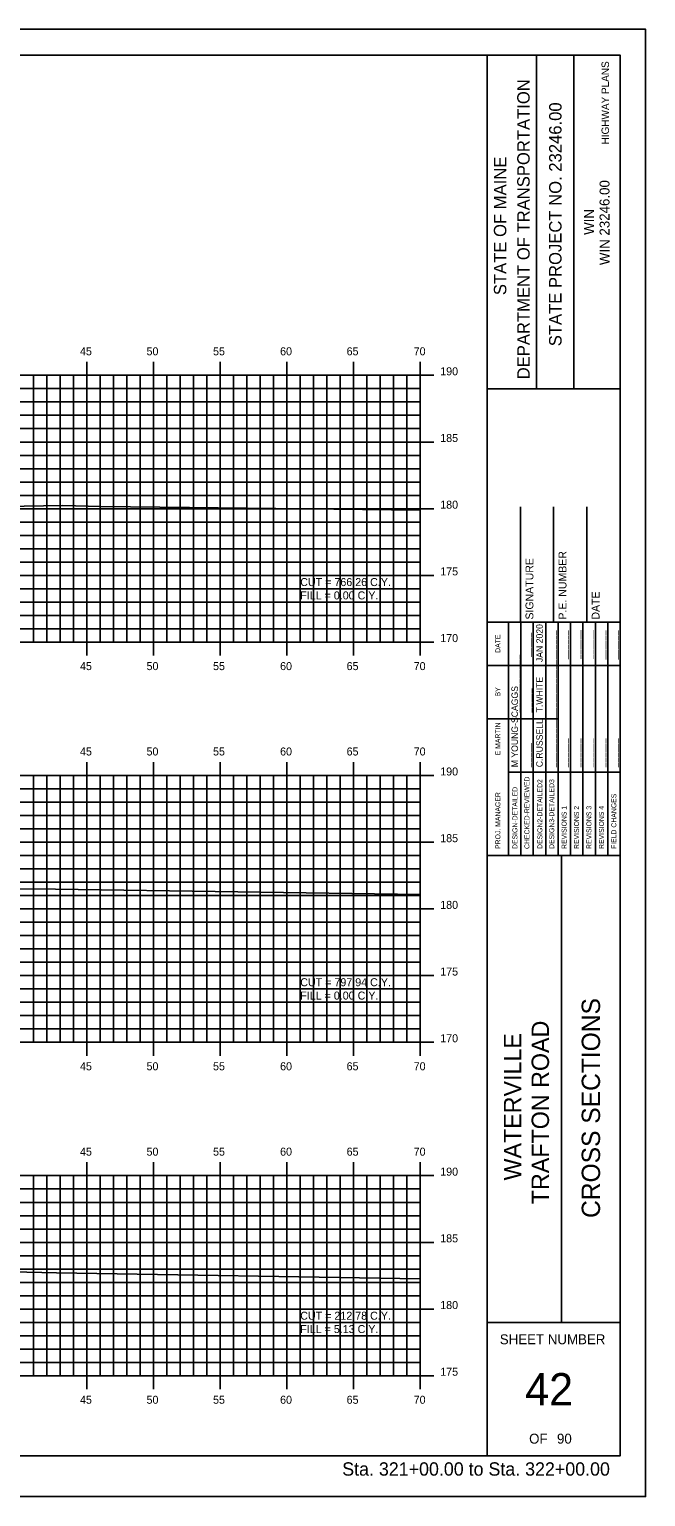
# Model space of a CAD drawing. Extents: x 1139872 to 1140042, y 608981 to 609091.
# Drawn here: x 1139995.6 to 1140041.9, y 608981.3 to 609091.3 of the extents above; entities that cross this region are included whole.
import ezdxf

# ---------------------------------------------------------------- set-up
doc = ezdxf.new("R2010")
doc.units = 0
for name, color, linetype in [('BORDER', 7, 'Continuous'), ('D_Text_Standard', 7, 'Continuous'), ('H_V ANNOTATION', 7, 'Continuous'), ('HIGHWAY_TITLE', 7, 'Continuous'), ('MAJOR', 7, 'Continuous'), ('MINOR', 7, 'Continuous'), ('PLOT BOUNDARY', 7, 'Continuous'), ('S_Roadway_Centerline', 7, 'Continuous')]:
    doc.layers.add(name, color=color, linetype=linetype)

msp = doc.modelspace()

# ---------------------------------------------------------------- linework, layer by layer
at = {"layer": 'BORDER'}
for p, q in [((1140029.98, 608984.34), (1140029.98, 609089.34)), ((1140033.7, 609064.33), (1140033.7, 609089.33)), ((1140036.5, 609064.33), (1140036.5, 609089.33)), ((1140029.98, 609064.33), (1140039.98, 609064.33)), ((1140032.48, 609046.84), (1140032.48, 609055.49)), ((1140034.98, 609046.84), (1140034.98, 609055.49)), ((1140037.48, 609046.84), (1140037.48, 609055.49)), ((1140029.98, 609046.84), (1140039.98, 609046.84)), ((1140029.98, 609029.34), (1140039.98, 609029.34)), ((1140035.57, 608994.34), (1140035.57, 609029.34)), ((1140029.98, 608994.34), (1140039.98, 608994.34))]:
    msp.add_line(p, q, dxfattribs=at)
msp.add_lwpolyline([(1139879.98, 608984.34), (1140039.98, 608984.34), (1140039.98, 609089.34), (1139879.98, 609089.34)], close=True, dxfattribs=at)
for points in [[(1140031.59, 609043.59), (1140031.59, 609046.84)], [(1140031.59, 609029.34), (1140031.59, 609046.13)], [(1140032.52, 609029.34), (1140032.52, 609046.84)], [(1140033.45, 609046.84), (1140033.45, 609029.34)], [(1140034.39, 609029.34), (1140034.39, 609046.84)], [(1140035.32, 609029.34), (1140035.32, 609046.84)], [(1140036.25, 609029.34), (1140036.25, 609046.84)], [(1140037.18, 609029.34), (1140037.18, 609046.84)], [(1140038.11, 609029.34), (1140038.11, 609046.84)], [(1140039.04, 609029.34), (1140039.04, 609046.84)], [(1140029.98, 609043.59), (1140039.98, 609043.59)], [(1140029.98, 609039.59), (1140031.59, 609039.59)], [(1140031.59, 609039.59), (1140035.32, 609039.59)], [(1140031.59, 609035.59), (1140039.98, 609035.59)]]:
    msp.add_lwpolyline(points, dxfattribs=at)
at = {"layer": 'MAJOR'}
for p, q in [((1139999.97, 609066.34), (1139999.97, 609065.34)), ((1140004.97, 609066.34), (1140004.97, 609065.34)), ((1140009.97, 609066.34), (1140009.97, 609065.34)), ((1140014.97, 609066.34), (1140014.97, 609065.34)), ((1140019.97, 609066.34), (1140019.97, 609065.34)), ((1140024.97, 609066.34), (1140024.97, 609065.34)), ((1139884.97, 609065.34), (1140024.97, 609065.34)), ((1139884.97, 609065.34), (1140024.97, 609065.34)), ((1139999.97, 609045.34), (1139999.97, 609065.34)), ((1140004.97, 609045.34), (1140004.97, 609065.34)), ((1140009.97, 609045.34), (1140009.97, 609065.34)), ((1140014.97, 609045.34), (1140014.97, 609065.34)), ((1140019.97, 609045.34), (1140019.97, 609065.34)), ((1140025.98, 609065.34), (1140023.97, 609065.34)), ((1140024.97, 609045.34), (1140024.97, 609065.34)), ((1140024.97, 609045.34), (1140024.97, 609065.34)), ((1139884.97, 609060.34), (1140024.97, 609060.34)), ((1140025.98, 609060.34), (1140023.97, 609060.34)), ((1139884.97, 609055.34), (1140024.97, 609055.34)), ((1140025.98, 609055.34), (1140023.97, 609055.34)), ((1139884.97, 609050.34), (1140024.97, 609050.34)), ((1140025.98, 609050.34), (1140023.97, 609050.34)), ((1139884.97, 609045.34), (1140024.97, 609045.34)), ((1139884.97, 609045.34), (1140024.97, 609045.34)), ((1139999.97, 609044.33), (1139999.97, 609045.34)), ((1140004.97, 609044.33), (1140004.97, 609045.34)), ((1140009.97, 609044.33), (1140009.97, 609045.34)), ((1140014.97, 609044.33), (1140014.97, 609045.34)), ((1140019.97, 609044.33), (1140019.97, 609045.34)), ((1140025.98, 609045.34), (1140023.97, 609045.34)), ((1140024.97, 609044.33), (1140024.97, 609045.34)), ((1139999.97, 609036.34), (1139999.97, 609035.34)), ((1140004.97, 609036.34), (1140004.97, 609035.34)), ((1140009.97, 609036.34), (1140009.97, 609035.34)), ((1140014.97, 609036.34), (1140014.97, 609035.34)), ((1140019.97, 609036.34), (1140019.97, 609035.34)), ((1140024.97, 609036.34), (1140024.97, 609035.34)), ((1139884.97, 609035.34), (1140024.97, 609035.34)), ((1139884.97, 609035.34), (1140024.97, 609035.34)), ((1139999.97, 609015.34), (1139999.97, 609035.34)), ((1140004.97, 609015.34), (1140004.97, 609035.34)), ((1140009.97, 609015.34), (1140009.97, 609035.34)), ((1140014.97, 609015.34), (1140014.97, 609035.34)), ((1140019.97, 609015.34), (1140019.97, 609035.34)), ((1140025.98, 609035.34), (1140023.97, 609035.34)), ((1140024.97, 609015.34), (1140024.97, 609035.34)), ((1140024.97, 609015.34), (1140024.97, 609035.34)), ((1139884.97, 609030.34), (1140024.97, 609030.34)), ((1140025.98, 609030.34), (1140023.97, 609030.34)), ((1139884.97, 609025.34), (1140024.97, 609025.34)), ((1140025.98, 609025.34), (1140023.97, 609025.34)), ((1139884.97, 609020.34), (1140024.97, 609020.34)), ((1140025.98, 609020.34), (1140023.97, 609020.34)), ((1139884.97, 609015.34), (1140024.97, 609015.34)), ((1139884.97, 609015.34), (1140024.97, 609015.34)), ((1139999.97, 609014.33), (1139999.97, 609015.34)), ((1140004.97, 609014.33), (1140004.97, 609015.34)), ((1140009.97, 609014.33), (1140009.97, 609015.34)), ((1140014.97, 609014.33), (1140014.97, 609015.34)), ((1140019.97, 609014.33), (1140019.97, 609015.34)), ((1140025.98, 609015.34), (1140023.97, 609015.34)), ((1140024.97, 609014.33), (1140024.97, 609015.34)), ((1139999.97, 609006.34), (1139999.97, 609005.34)), ((1140004.97, 609006.34), (1140004.97, 609005.34)), ((1140009.97, 609006.34), (1140009.97, 609005.34)), ((1140014.97, 609006.34), (1140014.97, 609005.34)), ((1140019.97, 609006.34), (1140019.97, 609005.34)), ((1140024.97, 609006.34), (1140024.97, 609005.34)), ((1139884.97, 609005.34), (1140024.97, 609005.34)), ((1139884.97, 609005.34), (1140024.97, 609005.34)), ((1139999.97, 608990.34), (1139999.97, 609005.34)), ((1140004.97, 608990.34), (1140004.97, 609005.34)), ((1140009.97, 608990.34), (1140009.97, 609005.34)), ((1140014.97, 608990.34), (1140014.97, 609005.34)), ((1140019.97, 608990.34), (1140019.97, 609005.34)), ((1140025.98, 609005.34), (1140023.97, 609005.34)), ((1140024.97, 608990.34), (1140024.97, 609005.34)), ((1140024.97, 608990.34), (1140024.97, 609005.34)), ((1139884.97, 609000.34), (1140024.97, 609000.34)), ((1140025.98, 609000.34), (1140023.97, 609000.34)), ((1139884.97, 608995.34), (1140024.97, 608995.34)), ((1140025.98, 608995.34), (1140023.97, 608995.34)), ((1139884.97, 608990.34), (1140024.97, 608990.34)), ((1139884.97, 608990.34), (1140024.97, 608990.34)), ((1139999.97, 608989.33), (1139999.97, 608990.34)), ((1140004.97, 608989.33), (1140004.97, 608990.34)), ((1140009.97, 608989.33), (1140009.97, 608990.34)), ((1140014.97, 608989.33), (1140014.97, 608990.34)), ((1140019.97, 608989.33), (1140019.97, 608990.34)), ((1140025.98, 608990.34), (1140023.97, 608990.34)), ((1140024.97, 608989.33), (1140024.97, 608990.34))]:
    msp.add_line(p, q, dxfattribs=at)
at = {"layer": 'MINOR'}
for p, q in [((1139995.97, 609045.34), (1139995.97, 609065.34)), ((1139996.97, 609045.34), (1139996.97, 609065.34)), ((1139997.97, 609045.34), (1139997.97, 609065.34)), ((1139998.97, 609045.34), (1139998.97, 609065.34)), ((1140000.97, 609045.34), (1140000.97, 609065.34)), ((1140001.97, 609045.34), (1140001.97, 609065.34)), ((1140002.97, 609045.34), (1140002.97, 609065.34)), ((1140003.97, 609045.34), (1140003.97, 609065.34)), ((1140005.97, 609045.34), (1140005.97, 609065.34)), ((1140006.97, 609045.34), (1140006.97, 609065.34)), ((1140007.97, 609045.34), (1140007.97, 609065.34)), ((1140008.97, 609045.34), (1140008.97, 609065.34)), ((1140010.97, 609045.34), (1140010.97, 609065.34)), ((1140011.97, 609045.34), (1140011.97, 609065.34)), ((1140012.97, 609045.34), (1140012.97, 609065.34)), ((1140013.97, 609045.34), (1140013.97, 609065.34)), ((1140015.97, 609045.34), (1140015.97, 609065.34)), ((1140016.97, 609045.34), (1140016.97, 609065.34)), ((1140017.97, 609045.34), (1140017.97, 609065.34)), ((1140018.97, 609045.34), (1140018.97, 609065.34)), ((1140020.97, 609045.34), (1140020.97, 609065.34)), ((1140021.97, 609045.34), (1140021.97, 609065.34)), ((1140022.97, 609045.34), (1140022.97, 609065.34)), ((1140023.97, 609045.34), (1140023.97, 609065.34)), ((1139884.97, 609064.34), (1140024.97, 609064.34)), ((1140024.97, 609064.34), (1140023.97, 609064.34)), ((1139884.97, 609063.34), (1140024.97, 609063.34)), ((1139884.97, 609062.34), (1140024.97, 609062.34)), ((1140024.97, 609063.34), (1140023.97, 609063.34)), ((1140024.97, 609062.34), (1140023.97, 609062.34)), ((1139884.97, 609061.34), (1140024.97, 609061.34)), ((1140024.97, 609061.34), (1140023.97, 609061.34)), ((1139884.97, 609059.34), (1140024.97, 609059.34)), ((1140024.97, 609059.34), (1140023.97, 609059.34)), ((1139884.97, 609058.34), (1140024.97, 609058.34)), ((1140024.97, 609058.34), (1140023.97, 609058.34)), ((1139884.97, 609057.34), (1140024.97, 609057.34)), ((1140024.97, 609057.34), (1140023.97, 609057.34)), ((1139884.97, 609056.34), (1140024.97, 609056.34)), ((1140024.97, 609056.34), (1140023.97, 609056.34)), ((1139884.97, 609054.34), (1140024.97, 609054.34)), ((1140024.97, 609054.34), (1140023.97, 609054.34)), ((1139884.97, 609053.34), (1140024.97, 609053.34)), ((1140024.97, 609053.34), (1140023.97, 609053.34)), ((1139884.97, 609052.34), (1140024.97, 609052.34)), ((1139884.97, 609051.34), (1140024.97, 609051.34)), ((1140024.97, 609052.34), (1140023.97, 609052.34)), ((1140024.97, 609051.34), (1140023.97, 609051.34)), ((1139884.97, 609049.34), (1140024.97, 609049.34)), ((1140024.97, 609049.34), (1140023.97, 609049.34)), ((1139884.97, 609048.34), (1140024.97, 609048.34)), ((1140024.97, 609048.34), (1140023.97, 609048.34)), ((1139884.97, 609047.34), (1140024.97, 609047.34)), ((1140024.97, 609047.34), (1140023.97, 609047.34)), ((1139884.97, 609046.34), (1140024.97, 609046.34)), ((1140024.97, 609046.34), (1140023.97, 609046.34)), ((1139995.97, 609015.34), (1139995.97, 609035.34)), ((1139996.97, 609015.34), (1139996.97, 609035.34)), ((1139997.97, 609015.34), (1139997.97, 609035.34)), ((1139998.97, 609015.34), (1139998.97, 609035.34)), ((1140000.97, 609015.34), (1140000.97, 609035.34)), ((1140001.97, 609015.34), (1140001.97, 609035.34)), ((1140002.97, 609015.34), (1140002.97, 609035.34)), ((1140003.97, 609015.34), (1140003.97, 609035.34)), ((1140005.97, 609015.34), (1140005.97, 609035.34)), ((1140006.97, 609015.34), (1140006.97, 609035.34)), ((1140007.97, 609015.34), (1140007.97, 609035.34)), ((1140008.97, 609015.34), (1140008.97, 609035.34)), ((1140010.97, 609015.34), (1140010.97, 609035.34)), ((1140011.97, 609015.34), (1140011.97, 609035.34)), ((1140012.97, 609015.34), (1140012.97, 609035.34)), ((1140013.97, 609015.34), (1140013.97, 609035.34)), ((1140015.97, 609015.34), (1140015.97, 609035.34)), ((1140016.97, 609015.34), (1140016.97, 609035.34)), ((1140017.97, 609015.34), (1140017.97, 609035.34)), ((1140018.97, 609015.34), (1140018.97, 609035.34)), ((1140020.97, 609015.34), (1140020.97, 609035.34)), ((1140021.97, 609015.34), (1140021.97, 609035.34)), ((1140022.97, 609015.34), (1140022.97, 609035.34)), ((1140023.97, 609015.34), (1140023.97, 609035.34)), ((1139884.97, 609034.34), (1140024.97, 609034.34)), ((1140024.97, 609034.34), (1140023.97, 609034.34)), ((1139884.97, 609033.34), (1140024.97, 609033.34)), ((1140024.97, 609033.34), (1140023.97, 609033.34)), ((1139884.97, 609032.34), (1140024.97, 609032.34)), ((1140024.97, 609032.34), (1140023.97, 609032.34)), ((1139884.97, 609031.34), (1140024.97, 609031.34)), ((1140024.97, 609031.34), (1140023.97, 609031.34)), ((1139884.97, 609029.34), (1140024.97, 609029.34)), ((1140024.97, 609029.34), (1140023.97, 609029.34)), ((1139884.97, 609028.34), (1140024.97, 609028.34)), ((1140024.97, 609028.34), (1140023.97, 609028.34)), ((1139884.97, 609027.34), (1140024.97, 609027.34)), ((1140024.97, 609027.34), (1140023.97, 609027.34)), ((1139884.97, 609026.34), (1140024.97, 609026.34)), ((1140024.97, 609026.34), (1140023.97, 609026.34)), ((1139884.97, 609024.34), (1140024.97, 609024.34)), ((1140024.97, 609024.34), (1140023.97, 609024.34)), ((1139884.97, 609023.34), (1140024.97, 609023.34)), ((1140024.97, 609023.34), (1140023.97, 609023.34)), ((1139884.97, 609022.34), (1140024.97, 609022.34)), ((1140024.97, 609022.34), (1140023.97, 609022.34)), ((1139884.97, 609021.34), (1140024.97, 609021.34)), ((1140024.97, 609021.34), (1140023.97, 609021.34)), ((1139884.97, 609019.34), (1140024.97, 609019.34)), ((1139884.97, 609018.34), (1140024.97, 609018.34)), ((1140024.97, 609019.34), (1140023.97, 609019.34)), ((1140024.97, 609018.34), (1140023.97, 609018.34)), ((1139884.97, 609017.34), (1140024.97, 609017.34)), ((1140024.97, 609017.34), (1140023.97, 609017.34)), ((1139884.97, 609016.34), (1140024.97, 609016.34)), ((1140024.97, 609016.34), (1140023.97, 609016.34)), ((1139995.97, 608990.34), (1139995.97, 609005.34)), ((1139996.97, 608990.34), (1139996.97, 609005.34)), ((1139997.97, 608990.34), (1139997.97, 609005.34)), ((1139998.97, 608990.34), (1139998.97, 609005.34)), ((1140000.97, 608990.34), (1140000.97, 609005.34)), ((1140001.97, 608990.34), (1140001.97, 609005.34)), ((1140002.97, 608990.34), (1140002.97, 609005.34)), ((1140003.97, 608990.34), (1140003.97, 609005.34)), ((1140005.97, 608990.34), (1140005.97, 609005.34)), ((1140006.97, 608990.34), (1140006.97, 609005.34)), ((1140007.97, 608990.34), (1140007.97, 609005.34)), ((1140008.97, 608990.34), (1140008.97, 609005.34)), ((1140010.97, 608990.34), (1140010.97, 609005.34)), ((1140011.97, 608990.34), (1140011.97, 609005.34)), ((1140012.97, 608990.34), (1140012.97, 609005.34)), ((1140013.97, 608990.34), (1140013.97, 609005.34)), ((1140015.97, 608990.34), (1140015.97, 609005.34)), ((1140016.97, 608990.34), (1140016.97, 609005.34)), ((1140017.97, 608990.34), (1140017.97, 609005.34)), ((1140018.97, 608990.34), (1140018.97, 609005.34)), ((1140020.97, 608990.34), (1140020.97, 609005.34)), ((1140021.97, 608990.34), (1140021.97, 609005.34)), ((1140022.97, 608990.34), (1140022.97, 609005.34)), ((1140023.97, 608990.34), (1140023.97, 609005.34)), ((1139884.97, 609004.34), (1140024.97, 609004.34)), ((1140024.97, 609004.34), (1140023.97, 609004.34)), ((1139884.97, 609003.34), (1140024.97, 609003.34)), ((1140024.97, 609003.34), (1140023.97, 609003.34)), ((1139884.97, 609002.34), (1140024.97, 609002.34)), ((1140024.97, 609002.34), (1140023.97, 609002.34)), ((1139884.97, 609001.34), (1140024.97, 609001.34)), ((1140024.97, 609001.34), (1140023.97, 609001.34)), ((1139884.97, 608999.34), (1140024.97, 608999.34)), ((1140024.97, 608999.34), (1140023.97, 608999.34)), ((1139884.97, 608998.34), (1140024.97, 608998.34)), ((1140024.97, 608998.34), (1140023.97, 608998.34)), ((1139884.97, 608997.34), (1140024.97, 608997.34)), ((1139884.97, 608996.34), (1140024.97, 608996.34)), ((1140024.97, 608997.34), (1140023.97, 608997.34)), ((1140024.97, 608996.34), (1140023.97, 608996.34)), ((1139884.97, 608994.34), (1140024.97, 608994.34)), ((1140024.97, 608994.34), (1140023.97, 608994.34)), ((1139884.97, 608993.34), (1140024.97, 608993.34)), ((1140024.97, 608993.34), (1140023.97, 608993.34)), ((1139884.97, 608992.34), (1140024.97, 608992.34)), ((1140024.97, 608992.34), (1140023.97, 608992.34)), ((1139884.97, 608991.34), (1140024.97, 608991.34)), ((1140024.97, 608991.34), (1140023.97, 608991.34))]:
    msp.add_line(p, q, dxfattribs=at)
at = {"layer": 'PLOT BOUNDARY'}
msp.add_lwpolyline([(1139871.88, 608981.28), (1140041.88, 608981.28), (1140041.88, 609091.28), (1139871.88, 609091.28)], close=True, dxfattribs=at)
at = {"layer": 'S_Roadway_Centerline'}
for points in [[(1139989.45, 609055.43), (1139998.16, 609055.57), (1140001.01, 609055.5), (1140007.66, 609055.44), (1140024.97, 609055.22)], [(1139930.9, 609027.93), (1139933.43, 609028.14), (1139933.86, 609028.13), (1139938.98, 609028.26), (1139943.57, 609028.25), (1139944.65, 609028.26), (1139954.54, 609028.42), (1139955.07, 609028.42), (1139966.33, 609028.09), (1139966.6, 609028.08), (1139966.8, 609028.06), (1139971.12, 609027.6), (1139975.1, 609027.23), (1139976.54, 609027), (1139980.49, 609026.99), (1139983.99, 609026.99), (1139989.76, 609026.88), (1139997.62, 609026.81), (1140024.97, 609026.42)], [(1139925.45, 608999.52), (1139927.43, 608999.6), (1139935.38, 608999.71), (1139940.06, 608999.68), (1139942.41, 608999.59), (1139945.2, 608999.58), (1139951.39, 608999.62), (1139955.85, 608999.66), (1139957.16, 608999.62), (1139967.26, 608999.38), (1139968.39, 608999.25), (1139969.51, 608999.07), (1139972.27, 608999.07), (1139994.37, 608998.12), (1139997.68, 608998.06), (1140024.97, 608997.61)]]:
    msp.add_lwpolyline(points, dxfattribs=at)

# ---------------------------------------------------------------- texts
at = {"layer": 'BORDER'}
for s, height, p in [('DEPARTMENT OF TRANSPORTATION', 0.9318, (1140033.18, 609065.04)), ('STATE PROJECT NO. 23246.00', 0.9318, (1140035.57, 609067.52)), ('STATE OF MAINE', 0.9318, (1140031.43, 609071.35)), ('WIN 23246.00', 0.7453, (1140039.17, 609073.6)), ('WIN', 0.745, (1140038.01, 609075.87)), ('SIGNATURE', 0.591, (1140033.46, 609047.03)), ('P.E. NUMBER', 0.5906, (1140035.94, 609047.03)), ('DATE', 0.591, (1140038.42, 609047.03)), ('DATE', 0.371, (1140030.98, 609044.54)), ('_____', 0.485, (1140033.19, 609044.24)), ('JAN 2020', 0.485, (1140034.16, 609043.84)), ('______', 0.485, (1140035.06, 609044.06)), ('______', 0.485, (1140035.99, 609044.06)), ('______', 0.485, (1140036.92, 609044.07)), ('______', 0.485, (1140037.85, 609044.07)), ('______', 0.485, (1140038.78, 609044.04)), ('______', 0.485, (1140039.71, 609044.04)), ('____________', 0.4845, (1140032.3, 609040.07)), ('____________', 0.4845, (1140035.06, 609040.07)), ('T.WHITE', 0.485, (1140034.16, 609040.07)), ('BY', 0.371, (1140030.98, 609041.27)), ('M YOUNG-SCAGGS', 0.4845, (1140032.3, 609035.96)), ('_____', 0.485, (1140033.23, 609040.07)), ('C.RUSSELL', 0.485, (1140034.16, 609035.96)), ('____________', 0.4845, (1140035.06, 609035.96)), ('E MARTIN', 0.373, (1140030.98, 609036.85)), ('______', 0.485, (1140035.99, 609035.96)), ('______', 0.485, (1140036.92, 609035.96)), ('______', 0.485, (1140037.85, 609035.96)), ('______', 0.485, (1140038.78, 609035.96)), ('______', 0.485, (1140039.71, 609035.96)), ('_____', 0.485, (1140033.19, 609035.96)), ('CHECKED-REVIEWED', 0.3727, (1140033.16, 609029.83)), ('DESIGN2-DETAILED2', 0.3727, (1140034.13, 609029.83)), ('DESIGN3-DETAILED3', 0.3727, (1140035.02, 609029.83)), ('PROJ. MANAGER', 0.3727, (1140030.98, 609029.83)), ('DESIGN-DETAILED', 0.3727, (1140032.26, 609029.83)), ('FIELD CHANGES', 0.3727, (1140039.68, 609029.83)), ('REVISIONS 1', 0.3727, (1140035.95, 609029.83)), ('REVISIONS 2', 0.3727, (1140036.88, 609029.83)), ('REVISIONS 3', 0.3727, (1140037.81, 609029.83)), ('REVISIONS 4', 0.3727, (1140038.75, 609029.83)), ('CROSS SECTIONS', 1.3779, (1140038.46, 609002.17))]:
    msp.add_text(s, height=height, rotation=90, dxfattribs=at).set_placement(p)
for s, height, p in [('SHEET NUMBER', 0.7453, (1140030.94, 608992.7)), ('42', 2.419, (1140032.84, 608988.12)), ('OF', 0.745, (1140033.14, 608985.25)), ('90', 0.745, (1140035.23, 608985.25))]:
    msp.add_text(s, height=height, dxfattribs=at).set_placement(p)
at = {"layer": 'D_Text_Standard'}
for s, p in [('CUT = 766.26 C.Y.', (1140015.97, 609049.54)), ('FILL = 0.00 C.Y.', (1140015.97, 609048.54)), ('CUT = 797.94 C.Y.', (1140015.97, 609019.54)), ('FILL = 0.00 C.Y.', (1140015.97, 609018.54)), ('CUT = 212.78 C.Y.', (1140015.97, 608994.54)), ('FILL = 5.13 C.Y.', (1140015.97, 608993.54))]:
    msp.add_text(s, height=0.6, dxfattribs=at).set_placement(p)
at = {"layer": 'H_V ANNOTATION'}
for s, height, p in [('45', 0.6, (1139999.45, 609066.84)), ('50', 0.6, (1140004.44, 609066.84)), ('55', 0.6, (1140009.43, 609066.84)), ('60', 0.6, (1140014.46, 609066.84)), ('65', 0.6, (1140019.45, 609066.84)), ('70', 0.6, (1140024.48, 609066.84)), ('190', 0.6, (1140026.47, 609065.34)), ('185', 0.6, (1140026.47, 609060.34)), ('180', 0.6, (1140026.47, 609055.34)), ('175', 0.6, (1140026.47, 609050.34)), ('170', 0.6, (1140026.47, 609045.34)), ('45', 0.6, (1139999.45, 609043.24)), ('50', 0.6, (1140004.44, 609043.24)), ('55', 0.6, (1140009.43, 609043.24)), ('60', 0.6, (1140014.46, 609043.24)), ('65', 0.6, (1140019.45, 609043.24)), ('70', 0.6, (1140024.48, 609043.24)), ('45', 0.6, (1139999.45, 609036.84)), ('50', 0.6, (1140004.44, 609036.84)), ('55', 0.6, (1140009.43, 609036.84)), ('60', 0.6, (1140014.46, 609036.84)), ('65', 0.6, (1140019.45, 609036.84)), ('70', 0.6, (1140024.48, 609036.84)), ('190', 0.6, (1140026.47, 609035.34)), ('185', 0.6, (1140026.47, 609030.34)), ('180', 0.6, (1140026.47, 609025.34)), ('175', 0.6, (1140026.47, 609020.34)), ('170', 0.6, (1140026.47, 609015.34)), ('45', 0.6, (1139999.45, 609013.24)), ('50', 0.6, (1140004.44, 609013.24)), ('55', 0.6, (1140009.43, 609013.24)), ('60', 0.6, (1140014.46, 609013.24)), ('65', 0.6, (1140019.45, 609013.24)), ('70', 0.6, (1140024.48, 609013.24)), ('45', 0.6, (1139999.45, 609006.84)), ('50', 0.6, (1140004.44, 609006.84)), ('55', 0.6, (1140009.43, 609006.84)), ('60', 0.6, (1140014.46, 609006.84)), ('65', 0.6, (1140019.45, 609006.84)), ('70', 0.6, (1140024.48, 609006.84)), ('190', 0.6, (1140026.47, 609005.34)), ('185', 0.6, (1140026.47, 609000.34)), ('180', 0.6, (1140026.47, 608995.34)), ('175', 0.6, (1140026.47, 608990.34)), ('45', 0.6, (1139999.45, 608988.24)), ('50', 0.6, (1140004.44, 608988.24)), ('55', 0.6, (1140009.43, 608988.24)), ('60', 0.6, (1140014.46, 608988.24)), ('65', 0.6, (1140019.45, 608988.24)), ('70', 0.6, (1140024.48, 608988.24)), ('Sta. 321+00.00 to Sta. 322+00.00', 1.0002, (1140019.12, 608982.85))]:
    msp.add_text(s, height=height, dxfattribs=at).set_placement(p)
at = {"layer": 'HIGHWAY_TITLE'}
for s, height, p in [('HIGHWAY PLANS', 0.559, (1140039.13, 609082.65)), ('TRAFTON ROAD', 1.3043, (1140034.63, 609003.2)), ('WATERVILLE', 1.304, (1140032.55, 609004.98))]:
    msp.add_text(s, height=height, rotation=90, dxfattribs=at).set_placement(p)

doc.saveas('drawing.dxf')
